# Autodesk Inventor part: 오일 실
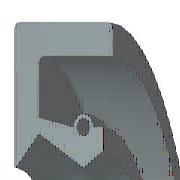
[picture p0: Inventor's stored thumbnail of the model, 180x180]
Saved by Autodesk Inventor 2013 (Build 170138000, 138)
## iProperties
IsCustomPart: 0
Created: 2014-10
Part Number: 오일 실
Material: 고무
Description: 오일-실
Document SubType Name: Modeling
Standard: KS B 2804
Designer: KYOUNG IL JANG
Standards Organization: KS
Language: ko-KR
Size Designation: D - 17 32 8
Categories: <MemberInstance><Categories><Category DisplayName="샤프트 부품" InternalName="7f7aeb1f-a693-4053-b835-cee3144e0d98" Mnemonic="SHFT"><Category DisplayName="실링" Intern
Density: 0.93 g/cm^3
Mass: 2.28027 g
Surface Area: 32.1224 cm^2
Volume: 2.45191 cm^3
Author: SeoGD™ [www.esajin.kr]
Revision Number: 1
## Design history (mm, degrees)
revolve "본체" stored, may be unused: angle "d17" = 90 deg
revolve "스프링1" stored, may be unused: angle "d18" = 90 deg
body "Solid1"
sketch "스케치1"
  geometry: L1 (0, 16)-(8, 16); L2 (8, 14.25)-(1.75, 14.25); L3 (1.75, 10.25)-(4.9, 8.5); L4 (4.9, 8.5)-(0, 8.5); L5 (0, 0)-(9.586, 0) reference; L6 (4.9, 8.5)-(6.3, 9.375); L7 (0, 18)-(0, -3) reference; L8 (-1.941, 0)-(11.507, 0) reference; L9 (4.2, 10.6)-(1.75, 11.21); L10 (1.75, 11.21)-(1.75, 14.25); L11 (0, 16)-(0, 8.588); L12 (4.9, 8.5)-(0, 8.5); L13 (1.75, 10.25)-(0.152, 8.528); L14 (8, 16)-(8, 14.25); L15 (5.6, 10.6)-(6.3, 10.6); L16 (6.3, 10.6)-(6.3, 9.375); C1 r 0.455 at (4.9, 10.6); A1 r 0.7 centre (4.9, 10.6) between (5.6, 10.6) and (4.2, 10.6); A2 r 0.088 centre (0.088, 8.588) between (0, 8.588) and (0.152, 8.528); 1 further point
  constraints: 28 end point, 5 horizontal alignment, 5 point on line, 4 point on circle, 4 vertical alignment, 3 centre point, 3 tangent, 2 collinear, 2 horizontal, 2 perpendicular, 1 coincident, 1 parallel
  dimensions: "d0" = 32 diameter of L1 L5 (= SD2); "d1" = 1.75 distance of L1.end L2.start (= SD); "d2" = 0.91 diameter of C1 (= SPDI); "d3" = 1.4 diameter of A1 (= SPDA); "d4" = 17 diameter of L3.end L5 (= NND); "d5" = 20.5 diameter of L3.start L5 (= TKDM); "d7" = 22.42 diameter of L9.end L5 (= TKDM + 0.24 x SWDT); "d8" = 1.75 distance between parallel lines of L11 L10 (= SD); "d9" = 4.9 distance from line of L11 C1.centre (= SPDST); "d10" = 21.2 diameter of C1.centre L5 (= HLDM); "d11" = 0.0875 radius of A2 (= 0.25 x LAB); "d12" = 6.3 distance between parallel lines of L11 L16 (= SDI); "d13" = 18.75 diameter of L6.end L5 (= ABDM); "d14" = 8 distance from line of L11 L1.end (= SWDT)
fillet "모깎기1" dims "d6" = 0.3 (= RR)
other parameters: "SD2" = 32 [user parameter; used in 1 equation term], "SWDT" = 8 [user parameter; used in 2 equation terms], "RR" = 0.3 [user parameter; used in 1 equation term], "SD" = 1.75 [user parameter; used in 2 equation terms], "NND" = 17 [user parameter; used in 1 equation term], "SPDA" = 1.4 [user parameter; used in 1 equation term], "SPDI" = 0.91 [user parameter; used in 1 equation term], "TKDM" = 20.5 [user parameter; used in 2 equation terms], "HLDM" = 21.2 [user parameter; used in 1 equation term], "ABDM" = 18.75 [user parameter; used in 1 equation term], "SDI" = 6.3 [user parameter; used in 1 equation term], "SPDST" = 4.9 [user parameter; used in 1 equation term], "LAB" = 0.35 [user parameter; used in 1 equation term], "d15" = 0, "d16" = 0, "d19" = 0
